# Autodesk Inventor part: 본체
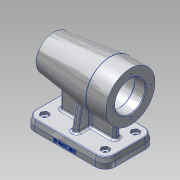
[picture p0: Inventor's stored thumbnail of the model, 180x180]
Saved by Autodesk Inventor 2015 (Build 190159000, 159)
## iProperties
Created: 2017-01
Part Number: 본체
Material: 알루미늄 6061
Document SubType Name: Modeling
Designer: Administrator
Density: 2.7 g/cm^3
Appearance: 알루미늄 - 평지
Mass: 792.237 g
Surface Area: 661.819 cm^2
Volume: 293.421 cm^3
Author: Administrator
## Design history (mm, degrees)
sketch "스케치1"
  geometry: L1 (42, 35)-(-42, 35); L2 (-56, 21)-(-56, -21); L3 (-42, -35)-(42, -35); L4 (56, -21)-(56, 21); L5 (56, 35)-(-56, -35); L6 (-56, 35)-(56, -35); L7 (38, 4)-(-38, 4); L8 (-38, 4)-(-38, -4); L9 (-38, -4)-(38, -4); L10 (38, -4)-(38, 4); L11 (38, 4)-(-38, -4); L12 (-38, 4)-(38, -4); A1 r 14 centre (42, -21) between (42, -35) and (56, -21); A2 r 14 centre (-42, -21) between (-56, -21) and (-42, -35); A3 r 14 centre (-42, 21) between (-42, 35) and (-56, 21); A4 r 14 centre (42, 21) between (56, 21) and (42, 35); 1 further point
  constraints: 24 end point, 8 point on circle, 8 point on line, 8 tangent, 4 centre point, 4 midpoint, 4 parallel, 3 equal radius, 2 horizontal, 2 perpendicular
  dimensions: "d0" = 112 distance of L5.end L6.end; "d1" = 70 distance of L6.start L5.end; "d2" = 8 distance of L7.end L8.end; "d3" = 18 distance between parallel lines of L10 L4; "d74" = 14 radius of A1
extrude "돌출1" new body sketch "스케치1" distance "d4" = 7; taper "d6" = 0 deg; dims "d5" = 7, "d7" = -15 deg
sketch "스케치2"
  geometry: L1 (-38, -4)-(38, -4); L2 (38, -4)-(38, 4); L3 (38, 4)-(-38, 4); L4 (-38, 4)-(-38, -4); L5 (-38, -4)-(38, 4); L6 (38, -4)-(-38, 4); L7 (-56, -21)-(-56, 21) reference; L8 (-42, 35)-(42, 35) reference; 4 further points
  constraints: 12 end point, 2 midpoint, 2 parallel, 1 horizontal, 1 perpendicular
  dimensions: "d9" = 8 distance of L1.end L2.end; "d10" = 18 distance between parallel lines of L4 L7
extrude "돌출2" join sketch "스케치2" distance "d12" = 60; taper "d13" = 0 deg
sketch "스케치3"
  geometry: L1 (7, 23)-(67, 12.42); L2 (67, 4)-(67, 12.42); L3 (67, 4)-(7, 4); L4 (7, 4)-(67, 4) reference; L5 (7, 4)-(7, 23); L6 (7, 4)-(7, 23); L7 (7, -21)-(7, 21) reference; L8 (0, 35)-(-7, 35) reference; 2 further points
  constraints: 10 end point, 2 collinear, 1 point on line, 1 vertical
  dimensions: "d18" = 100 deg angle of L7 L1; "d19" = 60 distance between parallel lines of L2 L5 (derived); "d89" = 12 distance from line of L1.start L8
extrude "돌출4" join sketch "스케치3" stored distance "d20" = 8; taper "d21" = 0 deg
sketch "스케치4"
  geometry: L1 (-56, 67)-(56, 67); L2 (-52.27, 91.144)-(28, 101); L3 (28, 101)-(56, 101); L4 (56, 101)-(56, 67); L5 (56, 88)-(41, 88); L6 (41, 88)-(41, 91); L7 (41, 91)-(-13, 91); L8 (-13, 91)-(-13, 88); L9 (-13, 88)-(-25, 88); L10 (-25, 88)-(-25, 84.5); L11 (-25, 84.5)-(-43, 84.5); L12 (-43, 84.5)-(-43, 83); L13 (-43, 83)-(-47, 83); L14 (-47, 83)-(-47, 77.5); L15 (-47, 77.5)-(-50, 77.5); L16 (-50, 77.5)-(-50, 67); L17 (38, 67)-(4, 67) reference; L18 (38, 67)-(56, 67); L19 (42, -7)-(56, -7) reference; A1 r 80 centre (24, 67) between (-52.27, 91.144) and (-56, 67); 1 further point
  constraints: 34 end point, 11 perpendicular, 6 point on line, 3 horizontal, 2 point on circle, 1 centre point
  dimensions: "d22" = 112 distance of L1.end L1.start; "d24" = 7 deg angle of L3 L2; "d25" = 80 radius of A1; "d27" = 34 distance between parallel lines of L3 L1; "d28" = 28 distance of L2.end L3.end; "d29" = 21 distance between parallel lines of L5 L1; "d30" = 15 distance of L5.start L5.end; "d31" = 54 distance of L6.end L7.end; "d32" = 12 distance of L8.end L9.end; "d33" = 21 distance between parallel lines of L9 L1 (derived); "d34" = 24 distance between parallel lines of L7 L1; "d35" = 17.5 distance between parallel lines of L11 L1; "d36" = 18 distance of L10.end L11.end; "d37" = 16 distance between parallel lines of L13 L1; "d38" = 10.5 distance between parallel lines of L15 L1; "d39" = 4 distance of L12.end L13.end; "d40" = 3 distance of L14.end L15.end; "d87" = 56 distance from line of L4 point (0, 0); "d88" = 74 distance between parallel lines of L1 L19 (derived)
revolve "회전1" stored, may be unused: angle "d42" = 90 deg
revolve "회전2" stored, may be unused: angle "d43" = 90 deg
sketch "스케치7"
  geometry: L1 (0, 0)-(0, 26); C1 r 21 at (0, 0) reference; 2 further points
  constraints: 2 end point, 1 coincident, 1 vertical
  dimensions: "d45" = 26 distance of L1.start L1.end
hole "구멍1" sketch "스케치7" at (0, 26) diameter "d46" = 3.242; stored, may be unused: countersink angle "d50" = 90 deg, drill point angle "d52" = 118 deg; dims "d47" = 8, "d48" = 4, "d49" = 2, "d51" = 11
sketch "스케치8"
  geometry: L1 (-42, -21)-(42, -21); L2 (42, -21)-(42, 21); L3 (42, 21)-(-42, 21); L4 (-42, 21)-(-42, -21); L5 (-42, -21)-(42, 21); L6 (42, -21)-(-42, 21); 5 further points
  constraints: 12 end point, 4 coincident, 2 midpoint, 2 parallel, 1 horizontal, 1 perpendicular
  dimensions: "d56" = 42 distance of L1.end L2.end; "d57" = 84 distance of L2.end L3.end
hole "구멍2" sketch "스케치8" at (-42, 21), (-42, -21), (42, -21), (42, 21) diameter "d58" = 5; stored, may be unused: countersink angle "d62" = 90 deg, drill point angle "d64" = 118 deg; dims "d59" = 8, "d60" = 10, "d61" = 4, "d63" = 11
sketch "스케치9"
  geometry: L1 (-39.113, 26)-(-36.226, 21); L2 (-36.226, 21)-(-39.113, 16); L3 (-39.113, 16)-(-44.887, 16); L4 (-44.887, 16)-(-47.774, 21); L5 (-47.774, 21)-(-44.887, 26); L6 (-44.887, 26)-(-39.113, 26); L7 (-42, 35)-(42, 35) reference; C1 r 5 at (-42, 21); 7 further points
  constraints: 12 end point, 3 coincident, 1 centre point, 1 midpoint, 1 parallel, 1 vertical alignment, 14 other
  dimensions: "d65" = 10 diameter of C1
extrude "돌출5" cut sketch "스케치9" distance "d66" = 4; taper "d67" = 0 deg
sketch "스케치10"
  geometry: L1 (98, 0)-(98, -7) reference; L2 (84, -7)-(0, -7) reference; 2 further points
  constraints: 1 other
  dimensions: "d81" = 56 distance from line of L1 point (42, -3); "d82" = 4 distance from line of point (42, -3) L2
extrude "돌출6" join sketch "스케치10" distance "d83" = 0.5; taper "d84" = 0 deg
fillet "모깎기1" dims "d85" = 1
fillet "모깎기2" dims "d86" = 3
fillet "모깎기3" dims "d90" = 3
fillet "모깎기4" dims "d91" = 3
chamfer "모따기1" distance "d92" = 1; stored, may be unused: second distance "d93" = 2, angle "d94" = 45 deg
fillet "모깎기5" dims "d95" = 3
fillet "모깎기6" dims "d96" = 0.3
node "솔리드1"
mirror "대칭1"
pattern_circular "원형 패턴1" dims angle "d54" = 360 deg
pattern_linear "직사각형 패턴2" dims "d77" = 42, "d80" = 84
